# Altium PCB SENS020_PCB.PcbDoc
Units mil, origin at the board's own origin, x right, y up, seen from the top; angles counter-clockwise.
Board outline 1830 x 1450 mil, 2 copper layers (Top Layer, Bottom Layer), stack 62 mil thick; 50 components, 16 nets, 144 pads, 61 vias.
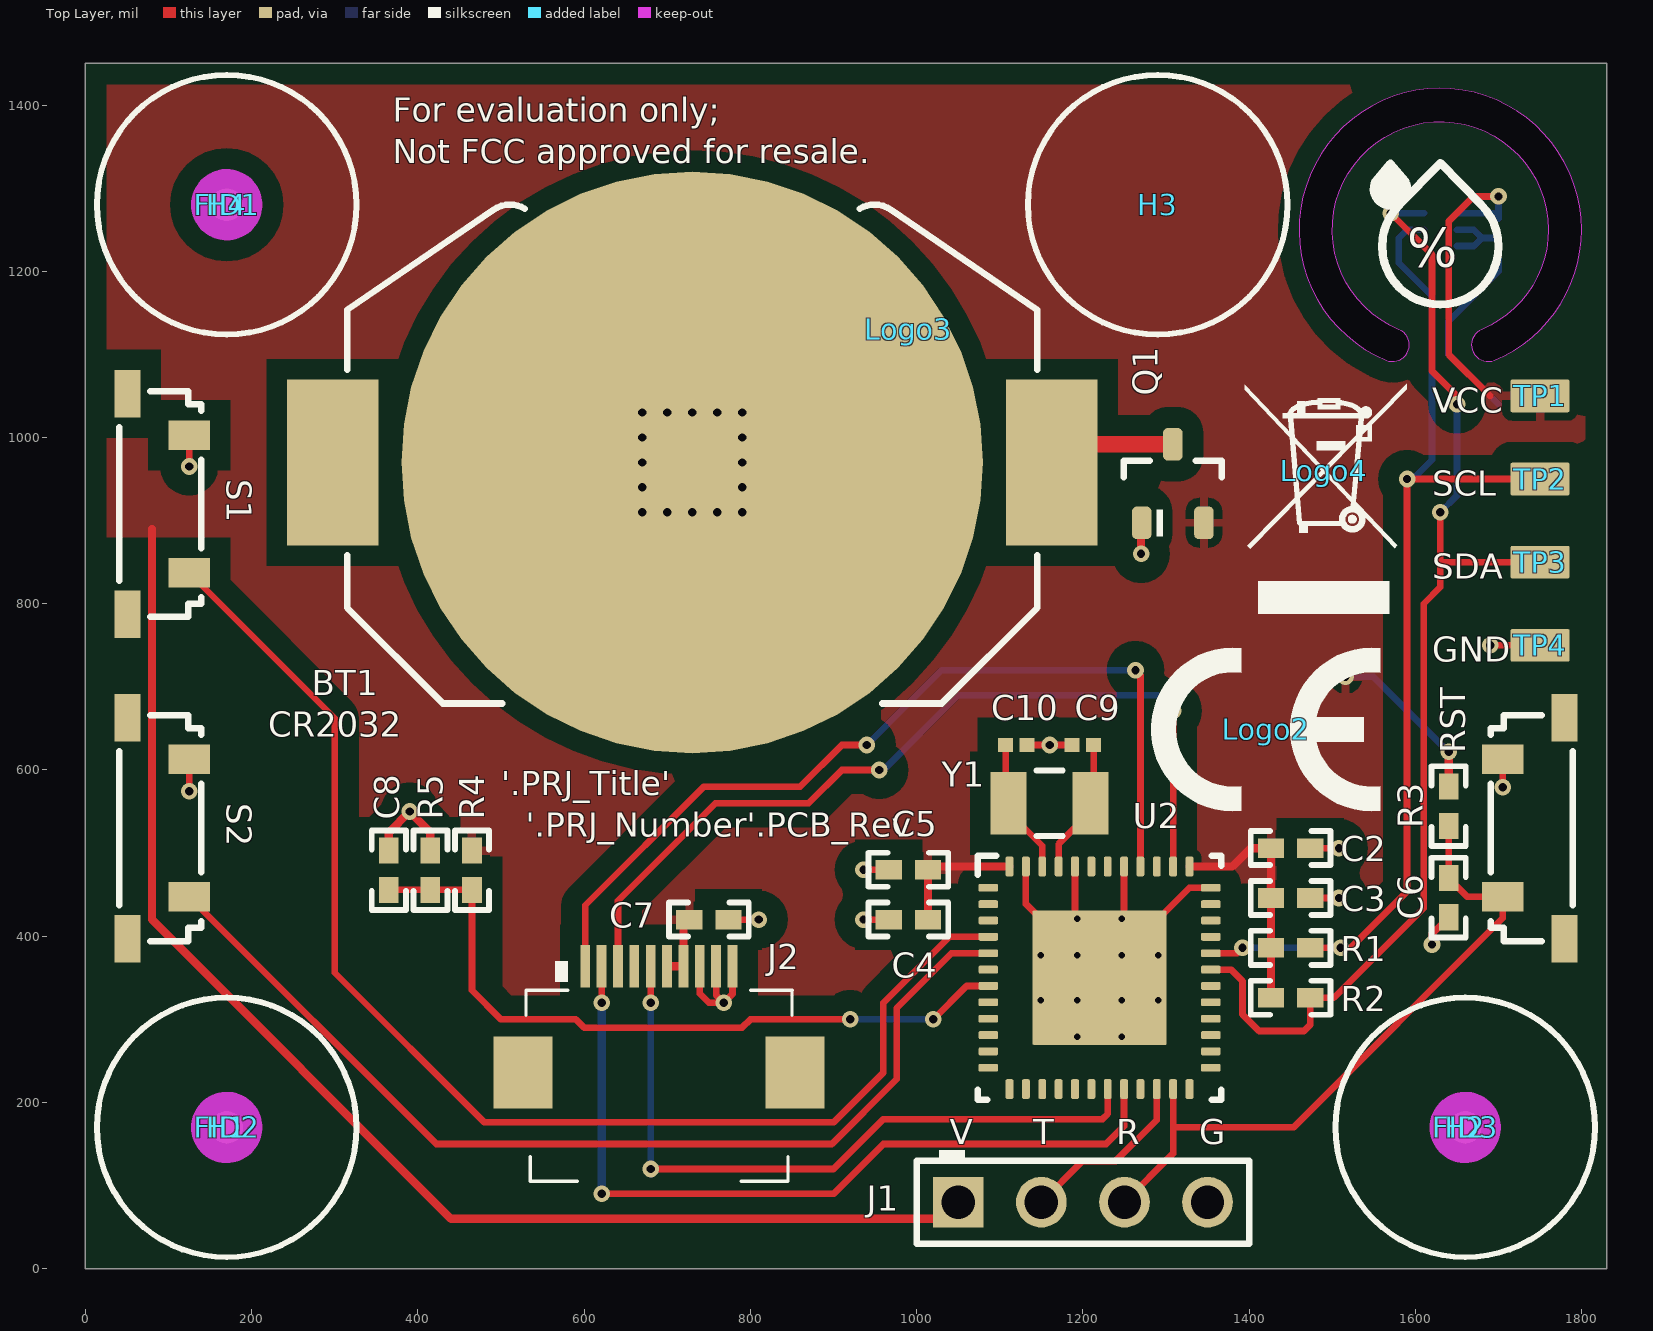
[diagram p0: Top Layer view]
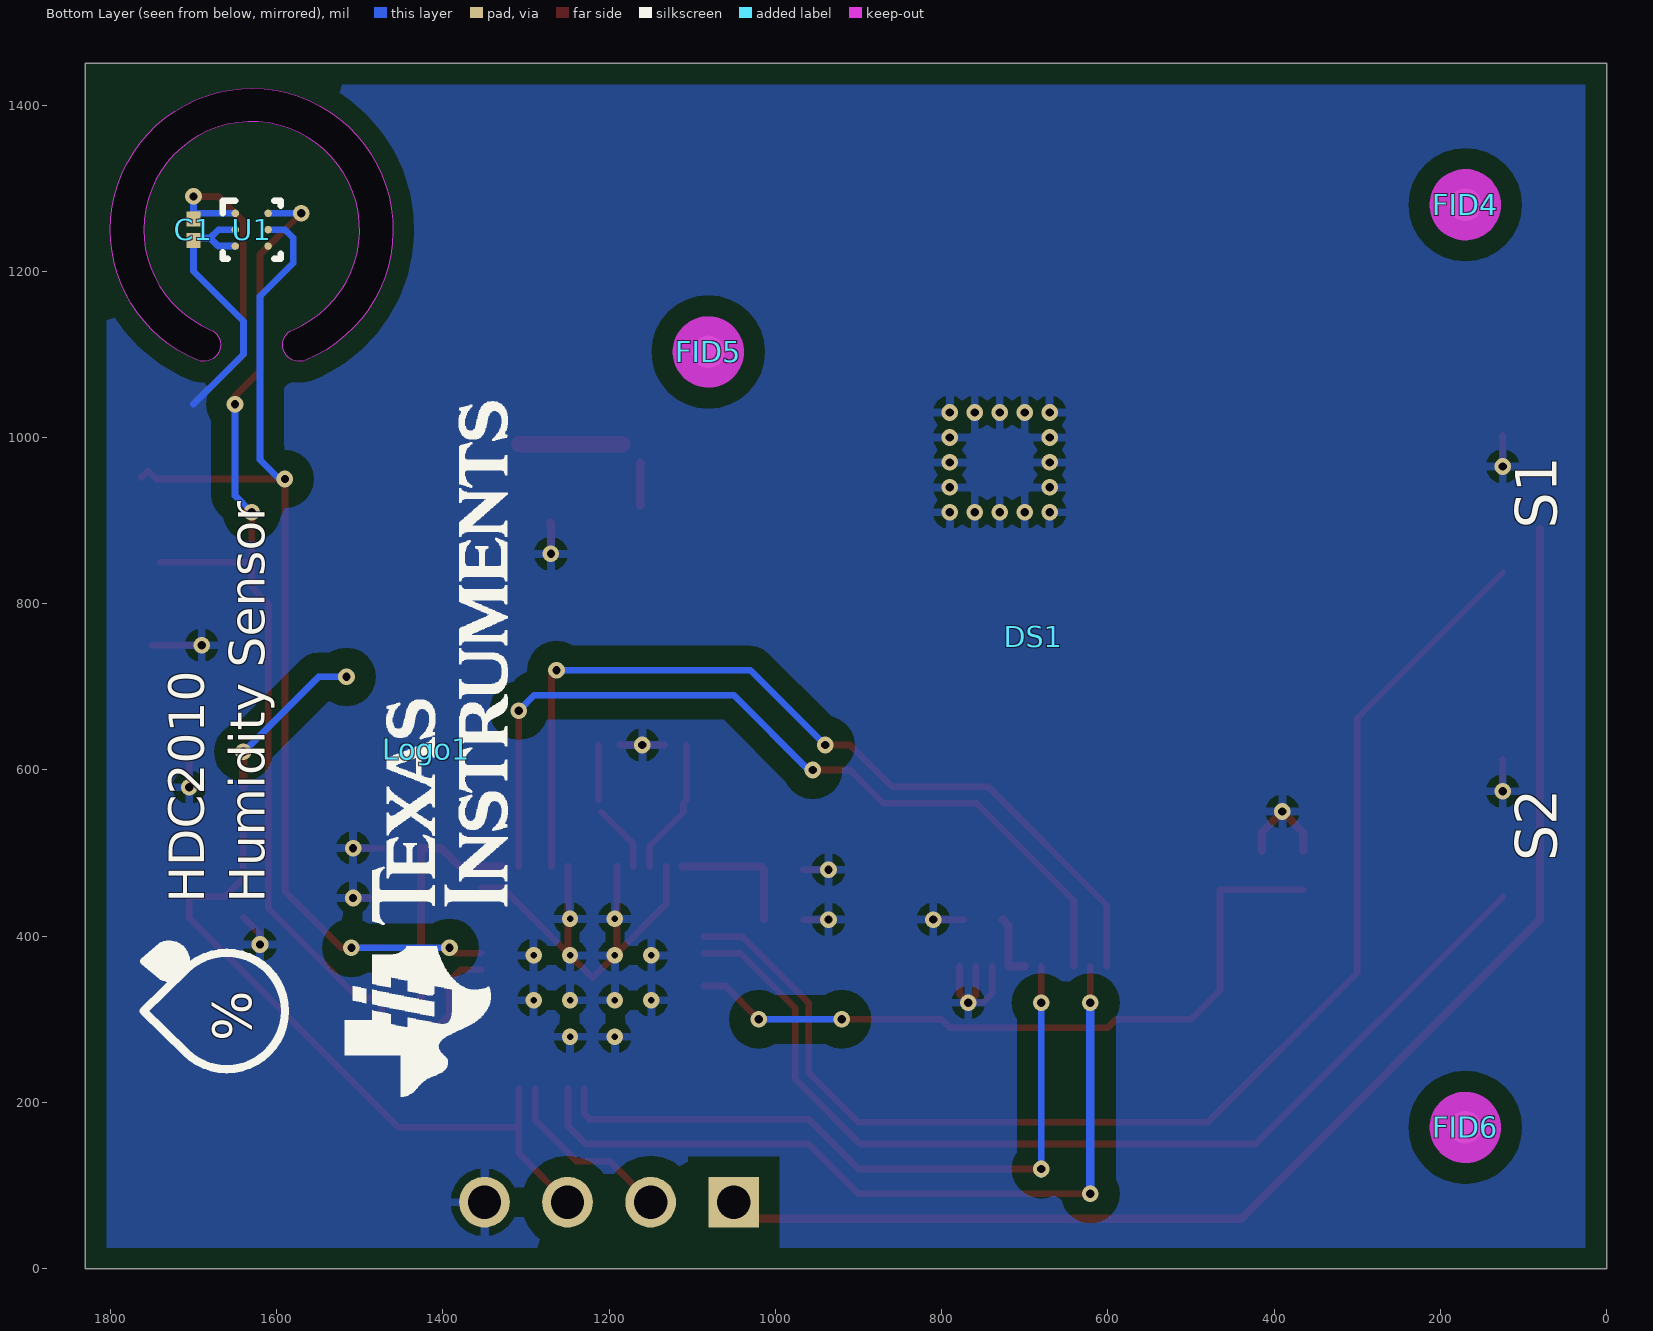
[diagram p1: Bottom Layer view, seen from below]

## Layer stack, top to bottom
Top Solder: solder mask 0.4, Solder Resist, Dk 3.5
Top Layer: signal copper 1.4
Dielectric1: core 59.2, FR-4, Dk 4.8
Bottom Layer: signal copper 1.4
Bottom Solder: solder mask 0.4, Solder Resist, Dk 3.5

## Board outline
0,0 0,1450 1830,1450 1830,0
cut-out: 1564.94,1092.93 ccw(c1572.6,1111.42) 1592.61,1111.42 ccw(c1572.6,1111.42) 1580.26,1129.91 cw(c1630,1250) 1759.99,1250 cw(c1630,1250) 1679.74,1129.91 ccw(c1687.4,1111.42) 1695.06,1092.93 ccw(c1630,1250) 1800.02,1250 ccw(c1630,1250)

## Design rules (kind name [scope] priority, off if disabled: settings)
AcuteAngle [All] p1: minimum=4.50000000000000E+0001 checktracksonly=FALSE
AssemblyTestPointUsage [All] p1: valid=2
BoardOutlineClearance BoardOutlineClearance_TO [OnLayer('Top Overlay') and not InRegion(1000,500,4000,800)] p1: gap=1 ignorepadtopadclearanceinfootprint=FALSE
BoardOutlineClearance BoardOutlineClearance_BO [OnLayer('Bottom Overlay') and not InRegion(1000,500,4000,800)] p2: gap=1 ignorepadtopadclearanceinfootprint=FALSE
BoardOutlineClearance BoardOutlineClearance_MountingHoles [OnCopper and InComponentClass('Mounting Holes')] p3: gap=40 ignorepadtopadclearanceinfootprint=FALSE
BoardOutlineClearance BoardOutlineClearance_Poly [OnCopper and IsPoly] p4: gap=25 ignorepadtopadclearanceinfootprint=FALSE
BoardOutlineClearance [OnCopper and Not InComponentClass('Logo') and not InComponentClass('FiducialMark') and not InPoly   and not InRegion(1000,500,4000,800)] p5: gap=10 ignorepadtopadclearanceinfootprint=FALSE
Clearance Clearance_Fiducial [IsKeepOut and InComponentClass('FiducialMark') vs IsPad and InComponentClass('FiducialMark')] p1: gap=0 ignorepadtopadclearanceinfootprint=FALSE
Clearance Clearance_Keepouts [((IsTrack Or IsArc) And Not InPoly) And IsFree and IsKeepOut vs ((IsTrack Or IsArc) And Not InPoly) And IsFree and IsKeepOut] p2: gap=0 ignorepadtopadclearanceinfootprint=FALSE
Clearance Clearance_Poly [InPolygon] p3: gap=25 ignorepadtopadclearanceinfootprint=FALSE except(0: Arc-Hole Track-Hole SMDPad-Hole THPad-Hole Via-Hole Fill-Hole Poly-Hole Region-Hole Text-Hole)
Clearance [All] p4: gap=7.87 ignorepadtopadclearanceinfootprint=FALSE except(0: Arc-Hole Track-Hole SMDPad-Hole THPad-Hole Via-Hole Fill-Hole Poly-Hole Region-Hole Text-Hole)
ComponentClearance ComponentClearance_FID [InComponentClass('FiducialMark') vs HasFootprint('Bumpon_SJ61A1')] p1: gap=0 collisioncheckmode=3 verticalgap=0 showdistances=FALSE
ComponentClearance ComponentClearance_LCD [HasFootprint('Sharp_LS013B7DH03')] p2: gap=0 collisioncheckmode=3 verticalgap=0 showdistances=FALSE
ComponentClearance ComponentClearance_MountingHoles_FiducialMarks [InComponentClass('Mounting Holes') vs InComponentClass('FiducialMark')] p3: gap=50 collisioncheckmode=3 verticalgap=10 showdistances=FALSE
ComponentClearance ComponentClearance_Shunt [InComponentClass('Header') vs InComponentClass('Shunt')] p4: gap=0 collisioncheckmode=3 verticalgap=0 showdistances=FALSE
ComponentClearance ComponentClearance_Logo [InComponentClass('Logo')] p5: gap=0 collisioncheckmode=3 verticalgap=0 showdistances=FALSE
ComponentClearance ComponentClearance_ScrewToNut [(HasFootprint('NY PMS 440 0025 PH')) vs (HasFootprint('Keystone_1902C'))] p6: gap=5 collisioncheckmode=3 verticalgap=10 showdistances=FALSE
ComponentClearance ComponentClearance_MountingHoles [InComponentClass('Mounting Holes')] p7: gap=250 collisioncheckmode=3 verticalgap=100000 showdistances=FALSE
ComponentClearance ComponentClearance_SmallPassives [HasFootprint('0201*') or HasFootprint('0402*') or HasFootprint('0508') or HasFootprint('0603*') or HasFootprint('0612') or HasFootprint('0805*') or HasFootprint('0815*') or HasFootprint('0830*') or HasFootprint('1206*') or HasFootprint('1210*') or HasFootprint('1808*') or HasFootprint('1812*') or HasFootprint('1825*') or HasFootprint('2010*') or HasFootprint('2220*') or HasFootprint('2225*') or HasFootprint('2512*') or HasFootprint('2728*') or HasFootprint('3518*') vs HasFootprint('0201*') or HasFootprint('0402*') or HasFootprint('0508') or HasFootprint('0603*') or HasFootprint('0612') or HasFootprint('0805*') or HasFootprint('0815*') or HasFootprint('0830*') or HasFootprint('1206*') or HasFootprint('1210*') or HasFootprint('1808*') or HasFootprint('1812*') or HasFootprint('1825*') or HasFootprint('2010*') or HasFootprint('2220*') or HasFootprint('2225*') or HasFootprint('2512*') or HasFootprint('2728*') or HasFootprint('3518*')] p8: gap=14.96 collisioncheckmode=3 verticalgap=10 showdistances=FALSE
ComponentClearance ComponentClearance_THtoSMT [IsThruComponent vs IsSMTComponent] p9: gap=40 collisioncheckmode=3 verticalgap=30 showdistances=FALSE
ComponentClearance ComponentClearance_THtoTH [IsThruComponent vs IsThruComponent] p10: gap=30 collisioncheckmode=3 verticalgap=30 showdistances=FALSE
ComponentClearance [All] p11: gap=30 collisioncheckmode=3 verticalgap=10 showdistances=FALSE
DiffPairsRouting [All] p1: maxlimit=100 minlimit=10 mostfreqgap=10 toplayer_minwidth=15 toplayer_maxwidth=15 toplayer_prefwidth=15 bottomlayer_minwidth=15 bottomlayer_maxwidth=15 bottomlayer_prefwidth=15 maxuncoupledlength=1000
FabricationTestPointUsage TestPointUsage [All] p1: valid=2 allowmultiple=FALSE
FabricationTestpoint Testpoint [All] p1: side=3 testpointundercomponent=TRUE minsize=40 maxsize=100 preferedsize=60 minholesize=0 maxholesize=40 preferedholesize=32 testpointgrid=1 allowsidetop=TRUE allowsidebottom=TRUE usegrid=TRUE gridtolerance=0.01
FanoutControl Fanout_LCC [IsLCC] p1: bgadir=Out bgaviamode=Centered fanoutstyle=Auto fanoutdirection=Alternating viagrid=1 // Fanout_LCC (Default Rule)
FanoutControl Fanout_BGA [IsBGA] p2: bgadir=Out bgaviamode=Centered fanoutstyle=Auto fanoutdirection=Alternating viagrid=1 // Fanout_BGA (Default Rule)
FanoutControl Fanout_Default [All] p4: bgadir=Out bgaviamode=Centered fanoutstyle=Auto fanoutdirection=Alternating viagrid=1 // Fanout_Default (Default Rule)
FanoutControl Fanout_Small [(CompPinCount < 5)] p5: bgadir=Out bgaviamode=Centered fanoutstyle=Auto fanoutdirection=OutThenIn viagrid=1 // Fanout_Small (Default Rule)
HoleSize [All] p1: absolutevalues=TRUE maxlimit=251 minlimit=7.87 maxpercent=80.000 minpercent=20.000
MinimumAnnularRing MinimumAnnularRing_ThermalPadVias [IsVia and InAnyComponent] p1: minimumring=5.91
MinimumAnnularRing [All] p2: minimumring=5
MinimumSolderMaskSliver MinimumSolderMaskSliver_Logo [InComponentClass('Logo') vs InComponentClass('Logo')] p1: minsoldermaskwidth=0.7
MinimumSolderMaskSliver [All] p2: minsoldermaskwidth=3.94
PlaneConnect [All] p1: planeconnectstyle=Relief reliefexpansion=10 reliefentries=4 reliefconductorwidth=10 reliefairgap=10
PolygonConnect [All] p1: connectstyle=Relief reliefconductorwidth=10 reliefentries=4 polygonreliefangle="90 Angle" airgapwidth=10
RoutingVias ThermalPadVias [IsVia and InAnyComponent] p1: holewidth=7.87 width=19.68 viastyle="Through Hole" minholewidth=7.87 minwidth=19.68 maxholewidth=12.99 maxwidth=23.62
RoutingVias [All] p2: holewidth=16 width=34 viastyle="Through Hole" minholewidth=7.87 minwidth=18 maxholewidth=40 maxwidth=65
SilkToBoardRegionClearance [Not ((IsComment or IsDesignator) And (Hide <> 'False')) and not InRegion(1000,500,4000,800)] p1:
SilkToSilkClearance SilkToSilkClearance_Pb-FreeLogo [(HasFootprint('Pb-Free_Overlay_Medium') OR HasFootprint('Pb-Free_Overlay_Small')) vs (HasFootprint('Pb-Free_Overlay_Medium') OR HasFootprint('Pb-Free_Overlay_Small'))] p1: silktosilkclearance=0
SilkToSilkClearance [All] p2: silktosilkclearance=4
SilkToSolderMaskClearance SilkToComponentPadClearance [(IsPad or IsFill or IsRegion) and InAnycomponent] p1: minsilkscreentomaskgap=5 clearancetoexposedcopper=TRUE
SilkToSolderMaskClearance "Silk to Solder Mask Opening" [All] p2: minsilkscreentomaskgap=4 clearancetoexposedcopper=FALSE
SolderMaskExpansion [All] p1: expansion=1.97
Width [All] p1: maxlimit=100 minlimit=6 preferedwidth=10 checkconnectedcopper=TRUE
15 further rules are at their usual default settings.

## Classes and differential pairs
component class Header: J1
component class AssemblyNote: ZZ1 ZZ2 ZZ3 ZZ4 ZZ5 ZZ6
component class FiducialMark: FID1 FID2 FID3 FID4 FID5 FID6
component class SENS020_Hardware: FID1 FID2 FID3 FID4 FID5 FID6 H1 H2 H3 H4 Logo1 Logo2 Logo3 Logo4 ZZ1 ZZ2 ZZ3 ZZ4 ZZ5 ZZ6
component class Logo: Logo1
component class SENS020_SCH: BT1 C1 C2 C3 C4 C5 C6 C7 C8 C9 C10 DS1 J1 J2 Q1 R1 R2 R3 R4 R5 RST S1 S2 TP1 TP2 TP3 TP4 U1 U2 Y1

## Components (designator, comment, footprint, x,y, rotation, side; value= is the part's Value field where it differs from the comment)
BT1 "BK-912" MPD_BK-912 730,970 r180 top locked
C1 "GRM033R61C104KE84D" 0201_033 1700,1250 r270 bottom value=0.1uF
C2 "GRM155R61A104KA01D" 0402 1450,506 r0 top value=0.1uF
C3 "GRM155R60J105KE19D" 0402 1450,446 r0 top value=1uF
C4 "GRM155R61A104KA01D" 0402 990,420 r180 top value=0.1uF
C5 "GRM155R60J105KE19D" 0402 990,480 r180 top value=1uF
C6 "GRM155R60J222KA01D" 0402 1640,446.38 r270 top value=2200pF
C7 "GRM155R61A104KA01D" 0402 750,420 r0 top value=0.1uF
C8 "GRM155R61A104KA01D" 0402 365,479.37 r90 top value=0.1uF
C9 "GRM0335C1H120JA01D" 0201 1200,630 r180 top value=12pF
C10 "GRM0335C1H120JA01D" 0201 1120,630 r0 top value=12pF
DS1 "LS013B7DH03" Sharp_LS013B7DH03 690,760 r180 bottom locked
FID1 "Fiducial" Fiducial10-20 170,1280 r0 top
FID2 "Fiducial" Fiducial10-20 170,170 r0 top
FID3 "Fiducial" Fiducial10-20 1660,170 r0 top
FID4 "Fiducial" Fiducial10-20 170,1280 r180 bottom
FID5 "Fiducial" Fiducial10-20 1080.71,1102.95 r180 bottom
FID6 "Fiducial" Fiducial10-20 170,170 r180 bottom
H1 "SJ61A1" Bumpon_SJ61A1 170,170 r0 top
H2 "SJ61A1" Bumpon_SJ61A1 1660,170 r0 top
H3 "SJ61A1" Bumpon_SJ61A1 1290,1280 r0 top
H4 "SJ61A1" Bumpon_SJ61A1 170,1280 r0 top
J1 "PBC04SAAN" Sullins_xxC04SAAN 1200,80 r0 top
J2 "FH12-10S-0.5SH[55]" Hirose_FH12-10S-0_5SH[55] 690,300 r0 top
Logo1 "Texas Instruments" TI_Stacked_Overlay_Small 1420,625.13 r90 bottom
Logo2 "CE Mark" CE_Mark_5mm 1420,648.76 r0 top (schematic designator LOGO2)
Logo3 "FCC disclaimer" FCC_disclaimer 990,1130 r0 top
Logo4 "WEEE logo" WEEE_Minimum 1490,960 r0 top
Q1 "SI2323DS" SOT-23 1308.19,944.58 r90 top value=-20V
R1 "CRCW040210K0JNED" 0402 1450,386 r180 top value=10k
R2 "CRCW040210K0JNED" 0402 1450,326 r180 top value=10k
R3 "CRCW040233K0JNED" 0402 1640,556.38 r90 top value=33k
R4 "CRCW04022M00FKED" 0402 465,479.37 r90 top value=2.00Meg
R5 "CRCW04022M00FKED" 0402 415,479.37 r270 top value=2.00Meg
RST "TL3330AF260QG" SW_TL3330 1740,530 r90 top
S1 "TL3330AF260QG" SW_TL3330 90,920 r270 top
S2 "TL3330AF260QG" SW_TL3330 90,530 r270 top
TP1 "S2761-46R" Harwin_S2761-46R 1750,1050 r0 top
TP2 "S2761-46R" Harwin_S2761-46R 1750,950 r0 top
TP3 "S2761-46R" Harwin_S2761-46R 1750,850 r0 top
TP4 "S2761-46R" Harwin_S2761-46R 1750,750 r0 top
U1 "HDC2010YPAR" YPA0006ABAB 1630,1250 r180 bottom
U2 "MSP430FR5969IRGZR" RGZ0048B 1220,350 r0 top
Y1 "ABS07-32.768KHZ-T" XTAL_ABS07 1160,560 r0 top
ZZ1 "These assemblies are ESD sensitive, ESD precautions shall be observed." AssemblyNote 180,3050 r0 top
ZZ2 "These assemblies must be clean and free from flux and all contaminants. Use of no clean flux is not acceptable." AssemblyNote 180,2970 r0 top
ZZ3 "These assemblies must comply with workmanship standards IPC-A-610 Class 2, unless otherwise specified." AssemblyNote 180,2880 r0 top
ZZ4 "These assemblies must not be washed after the HDC device is mounted." AssemblyNoteLabel 180,2710 r0 top
ZZ5 "These assemblies must not have flux contamination between the HDC device and the PCB." AssemblyNoteLabel 180,2630 r0 top
ZZ6 "Recommended to assemble and wash top side components before assembling HDC on bottom side." AssemblyNoteLabel 180,2550 r0 top

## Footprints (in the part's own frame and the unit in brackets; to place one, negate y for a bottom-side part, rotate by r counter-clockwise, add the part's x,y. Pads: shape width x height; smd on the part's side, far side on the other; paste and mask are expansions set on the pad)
0201 [mm] "Data from Kemet datasheet CC101_COM dated 7/28/11"
  rect 0.46x0.42 smd mask+0.048: 1(-0.33,0) 2(0.33,0)
  body extent -0.31,-0.16 0.31,0.16, height 0.26
0201_033 [mm] "SMD, 2-Leads, Height 0.33mm"
  rect 0.46x0.42 smd mask+0.048: 1(-0.33,0) 2(0.33,0)
  body extent -0.31,-0.16 0.31,0.16, height 0.33
0402 [mm] "0402 from SM-752 data"
  rect 0.8x0.6 smd: 1(-0.6,0) 2(0.6,0)
  silkscreen extent -1.22,-0.52 1.22,0.52, body extent -0.55,-0.3 0.55,0.3, height 0.6
AssemblyNote [mil] "Assembly Note"
AssemblyNoteLabel [mil] "Assembly Note for PCB Labels"
Bumpon_SJ61A1 [mil] "3M Cylindrical Bumpon black"
  round 1 on Mech3: 0(0,0)
  silkscreen extent -156,-156 156,156, body extent -156,-155 156,156, height 201
CE_Mark_5mm [mil] "Minimum text height for CE Mark"
  silkscreen extent -138,-98 138,98
FCC_disclaimer [mil]
Fiducial10-20 [mm]
  round 1 smd mask+0.5: 1(0,0)
  Top Layer keep-out circle w1.178: c0,0 r0.5
Harwin_S2761-46R [mm] "Natural PC Test Point Brass, SMT"
  rrect10% 1.8x1 smd: 1(0,0)
  body extent -0.8,-0.4 0.8,0.4, height 1.15
Hirose_FH12-10S-0_5SH[55] [mm] "Hirose, footprint recommended"
  rect 0.3x1.3 smd: 1(-2.254,1.626) 2(-1.754,1.626) 3(-1.254,1.626) 4(-0.754,1.626) 5(-0.253,1.626) 6(0.246,1.626) 7(0.746,1.626) 8(1.246,1.626) 9(1.746,1.626) 10(2.247,1.626)
  rect 1.8x2.2 smd: M1(-4.153,-1.622) M2(4.153,-1.626)
  silkscreen extent -4.06,-4.95 4.07,1.78, body extent -4.55,-4.88 4.56,0.84, height 2
MPD_BK-912 [mm] "Battery Holder for CR2032, SMT"
  rect 2.79x5.08 smd: 1(-10.985,0) 2(10.985,0)
  round 17.78 smd paste-9: 3(0,0)
  silkscreen extent -10.54,-7.88 10.54,7.37, body extent -11.43,-7.88 11.43,7.37, height 4.33
RGZ0048B [mm] "QFN, 48-Leads, Body 7x7mm, Pitch 0.5mm, Thermal Pad 5.15x5.15mm, TI Recommended"
  rrect42% 0.6x0.24 smd: 1(-3.4,2.75) 2(-3.4,2.25) 3(-3.4,1.75) 4(-3.4,1.25) 5(-3.4,0.75) 6(-3.4,0.25) 7(-3.4,-0.25) 8(-3.4,-0.75) 9(-3.4,-1.25) 10(-3.4,-1.75) 11(-3.4,-2.25) 12(-3.4,-2.75) 25(3.4,-2.75) 26(3.4,-2.25) 27(3.4,-1.75) 28(3.4,-1.25) 29(3.4,-0.75) 30(3.4,-0.25) 31(3.4,0.25) 32(3.4,0.75) 33(3.4,1.25) 34(3.4,1.75) 35(3.4,2.25) 36(3.4,2.75)
  rrect42% 0.24x0.6 smd: 13(-2.75,-3.4) 14(-2.25,-3.4) 15(-1.75,-3.4) 16(-1.25,-3.4) 17(-0.75,-3.4) 18(-0.25,-3.4) 19(0.25,-3.4) 20(0.75,-3.4) 21(1.25,-3.4) 22(1.75,-3.4) 23(2.25,-3.4) 24(2.75,-3.4) 37(2.75,3.4) 38(2.25,3.4) 39(1.75,3.4) 40(1.25,3.4) 41(0.75,3.4) 42(0.25,3.4) 43(-0.25,3.4) 44(-0.75,3.4) 45(-1.25,3.4) 46(-1.75,3.4) 47(-2.25,3.4) 48(-2.75,3.4)
  rrect9% 1.17x1.17 on Top Paste: 49(-1.37,-1.37) 49(-1.37,0) 49(-1.37,1.37) 49(0,-1.37) 49(0,0) 49(0,1.37) 49(1.37,-1.37) 49(1.37,0) 49(1.37,1.37)
  rrect2% 4.1x4.1 smd paste-2.575: 49(0,0)
  silkscreen extent -3.72,-3.72 3.72,3.72, body extent -3.5,-3.5 3.5,3.5, height 1.01
Sharp_LS013B7DH03 [mil] "LCD Display Dot Pixels 128x128"
  body extent -524,-1167 524,563, height 29
SOT-23 [mm] "SOT23, 3-Leads, Body 2.9x1.3mm, Pitch 0.95mm, Lead Span 2.5mm, IPC Medium Density"
  rrect50% 1x0.6 smd: 1(-1.2,0.95) 2(-1.2,-0.95) 3(1.2,0)
  silkscreen extent -1.62,-1.5 0.7,1.5, body extent -1.16,-1.45 1.21,1.45, height 1
Sullins_xxC04SAAN [mm] "Header, 2.54 mm, 4x1, TH"
  rect 1.55x1.55 hole 1.016: 1(-3.81,0)
  round 1.55 hole 1.016: 2(-1.27,0) 3(1.27,0) 4(3.81,0)
  silkscreen extent -5.08,-1.27 5.08,1.6, body extent -5.08,-1.27 5.08,1.27, height 8.38
SW_TL3330 [mm] "SMD, 4-Leads, Body 7.8x3.5mm"
  rect 0.9x1.27 smd: 1(-2.1,0.885) 2(2.1,0.885)
  rect 1.45x0.8 smd: 3(-3.375,-1) 4(3.375,-1)
  silkscreen extent -3.45,-1.25 3.45,1.25, body extent -3.9,-2.25 3.9,1.35, height 3.5
TI_Stacked_Overlay_Small [mil]
  silkscreen extent -418,-98 418,98
WEEE_Minimum [mil] "WEEElie bin"
  silkscreen extent -95,-172 99,104
XTAL_ABS07 [mm] "ABRACON"
  rect 1.1x1.9 smd: 1(-1.25,0) 2(1.25,0)
  silkscreen extent -0.4,-1 0.4,1, body extent -1.65,-0.8 1.65,0.8, height 0.9
YPA0006ABAB [mm] "BGA, 6-Leads, Body1.505x1.505mm, Pitch 0.5mm"
  round 0.23 smd paste-0.13 mask+0.038: A1(-0.5,0.5) A2(0.5,0.5) B1(-0.5,0) B2(0.5,0) C1(-0.5,-0.5) C2(0.5,-0.5)
  silkscreen extent -0.89,-0.89 0.89,0.89, body extent -0.75,-0.75 0.75,0.75, height 0.68

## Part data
BT1: library part CMP-0003749-2, "Battery Holder for CR2032, SMT", Manufacturer="Memory Protection Devices", Supplier Part Number 1=BK-912-ND
C1: library part CMP-0009717-2, "CAP, CERM, 0.1 uF, 16 V, +/- 10%, X5R, 0201", Cap_Case=0201, Manufacturer=MuRata, Supplier Part Number 1=490-9985-1-ND, TempCo=X5R, Tolerance_%=10%, Value1=Unknown, Value2=16V, ValueDisplayed=0.1uF
C2 C4 C7 C8: library part CMP-0006562-2, "CAP, CERM, 0.1 uF, 10 V, +/- 10%, X5R, 0402", Cap_Case=0402, Manufacturer=MuRata, Supplier Part Number 1=490-1318-1-ND, TempCo=X5R, Tolerance_%=10%, Value1=Unknown, Value2=10V, ValueDisplayed=0.1uF
C3 C5: library part CMP-0006532-2, "CAP, CERM, 1 uF, 6.3 V, +/- 10%, X5R, 0402", Cap_Case=0402, Manufacturer=MuRata, Supplier Part Number 1=490-1320-1-ND, TempCo=X5R, Tolerance_%=10%, Value1=Unknown, Value2=6.3V, ValueDisplayed=1uF
C6: library part CMP-0006540-2, "CAP, CERM, 2200 pF, 6.3 V, +/- 10%, X5R, 0402", Cap_Case=0402, Manufacturer=MuRata, Supplier Part Number 1=GRM155R60J222KA01D-ND, TempCo=X5R, Tolerance_%=10%, Value1=Unknown, Value2=6.3V, ValueDisplayed=2200pF
C9 C10: library part CMP-0009664-3, "CAP, CERM, 12 pF, 50 V, +/- 5%, C0G/NP0, 0201", Cap_Case=0201, Manufacturer=MuRata, Supplier Part Number 1=490-6114-1-ND, TempCo=C0G/NP0, Tolerance_%=5%, Value1=Unknown, Value2=50V, ValueDisplayed=12pF
DS1: library part CMP-0067626-1, "LCD Display Dot Pixels 128x128", Manufacturer="Sharp Microelectronics", Supplier Part Number 1=425-2903-ND
FID1 FID2 FID3 FID4 FID5 FID6: library part CMP-0077181-1, "Fiducial mark.  There is nothing to buy or mount.", Manufacturer=N/A
H1 H2 H3 H4: library part CMP-0003621-1, "Bumpon, Cylindrical, 0.312 X 0.200, Black", Manufacturer=3M, Supplier Part Number 1=SJ5746-0-ND
J1: library part CMP-0054583-1, "Header, 2.54 mm, 4x1, Gold, TH", Color=Black, Current_A=3A, Manufacturer="Sullins Connector Solutions", Supplier Part Number 1=S1011E-04-ND, Voltage_V=1.8kV
J2: library part CMP-0075009-2, "Connector, FPC 10 Pos. 9.1x2.0x5.6 mm", Manufacturer="Hirose Electric Co. Ltd.", PartNumber=FH12-10S-0.5SH(55), Supplier Part Number 1=HFJ110CT-ND
Logo1: library part CMP-0074838-1, "Texas Instrument Corporate Signature"
Logo2: library part CMP-0074844-1
Logo3: library part CMP-0074847-1, "FCC_disclaimer"
Logo4: library part CMP-0074769-1
Q1: library part CMP-0000092-2, "MOSFET, P-CH, -20 V, -3.7 A, SOT-23", Alternate Manufacturer=None, Manufacturer=Vishay-Siliconix, Value1=0.03, Value2="12.5 nC"
R1 R2: library part CMP-0026825-4, "RES, 10 k, 5%, 0.063 W, 0402", Manufacturer=Vishay-Dale, Power_W=63mW, Supplier Part Number 1=541-10KJCT-ND, TempCo="200 ppm/C", Tolerance_%=5%, Value2=0.063W, Value_Code=10k0, ValueDisplayed=10k
R3: library part CMP-0026907-2, "RES, 33 k, 5%, 0.063 W, 0402", Manufacturer=Vishay-Dale, Power_W=63mW, Supplier Part Number 1=541-33KJCT-ND, TempCo="200 ppm/C", Tolerance_%=5%, Value2=0.063W, Value_Code=33k0, ValueDisplayed=33k
R4 R5: library part CMP-0026245-1, "RES, 2.00 M, 1%, 0.063 W, 0402", Manufacturer=Vishay-Dale, Power_W=63mW, Supplier Part Number 1=541-2.00MLCT-ND, TempCo="100 ppm/C", Tolerance_%=1%, Value2=0.063W, Value_Code=2M00, ValueDisplayed=2.00M
RST S1 S2: library part CMP-0002231-1, "Switch, SPST-NO,  1 Pos, 0.05A, 12VDC, SMD", CurrentRating_mA=50A, Manufacturer=E-Switch, Supplier Part Number 1=EG4389CT-ND
TP1 TP2 TP3 TP4: library part CMP-0067619-1, "Natural PC Test Point Brass, SMT", Manufacturer=Harwin, Supplier Part Number 1=952-2665-1-ND
U1: library part CMP-0014223-2, "HDC2010 Low Power Humidity and Temperature Digital Sensor, YPA0006ABAB (DSBGA-6)", Alternate Manufacturer="Texas Instruments", Alternate PartNumber=HDC2010YPAT
U2: library part CMP-0066503-2, "MSP430FR5969 16 MHz Ultra-Low-Power Microcontroller featuring 64 KB FRAM, 2 KB SRAM, 40 IO, RGZ0048B (VQFN-48)", Alternate Manufacturer="Texas Instruments", Alternate PartNumber=MSP430FR5969IRGZT
Y1: library part CMP-0004628-3, "CRYSTAL, 32.768KHz, 12.5PF, SMD", Frequency_Fixed=32.768kHz, Frequency Stability=+/-20ppm, Manufacturer="Abracon Corporation", Supplier Part Number 1=535-9542-1-ND
ZZ1: library part CMP-0077236-1
ZZ2: library part CMP-0077237-1
ZZ3: library part CMP-0077238-1
ZZ4 ZZ5 ZZ6: library part CMP-0003616-3, "This Assembly Note is for PCB labels only"

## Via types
v1: diameter 20, hole 10, Top Layer to Bottom Layer, tented both sides, 47 vias
v2: diameter 19.68, hole 7.87, Top Layer to Bottom Layer, 12 vias
v3: diameter 20, hole 10, Top Layer to Bottom Layer, 2 vias

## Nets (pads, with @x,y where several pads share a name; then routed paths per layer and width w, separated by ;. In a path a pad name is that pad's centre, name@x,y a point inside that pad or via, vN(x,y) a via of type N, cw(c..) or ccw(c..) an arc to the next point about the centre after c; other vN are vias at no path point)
DISP: J2.5 U2.19 | length 857.8
  Top Layer w8: v1(680,120) 900,120 960,180 1223.62,180 1229.84,186.22 U2.19 ; v1(680.02,320) J2.5
  Bottom Layer w8: v1@680.02,113.37 v1(680.02,320)
GND: BT1.3 C1.2 C2.2 C3.2 C4.2 C5.2 C6.2 C7.2 C8.2 C9.2 C10.2 J1.4 J2.8 J2.9 J2.10 Q1.1 R5.1 RST.2 S1.1 S2.1 TP4.1 U1.B1 U1.C1 U2.36 U2.41 U2.44 U2.47 U2.49@1220,350 | length 1635.9
  Top Layer w8: v1(124.84,574.37) S2.1 ; v1(124.84,965.16) S1.1 ; J2.8 739.07,330.93 750,320 v1(768,320) ; J2.9 758.76,329.24 v1(768,320) ; C7.2 v1(810,420) ; J2.10 778.44,330.44 v1(768,320) ; v1(936,420) C4.2 ; v1(936,480) C5.2 ; U2.47 1131.42,438.58 U2.49@1190.47,379.53 ; C10.2 v3(1160,630) C9.2 ; U2.44 U2.49@1190.47,379.53 ; U2.41 U2.49@1249.53,379.53 ; U2.36 1328.27,458.27 U2.49@1249.53,379.53 ; C3.2 v1(1508,446) ; C2.2 v1(1508,506) ; v1(1620,390) 1620,402.76 C6.2 ; v1(1690,750) TP4.1 ; v1(1705.16,579.25) RST.2 ; U2.49@1190.47,379.53 v2(1193.03,376.97) 1220,350 v2(1246.97,376.97) U2.49@1249.53,379.53
  Top Layer w10: C8.2 365,525 v1(390,550) 415,525 R5.1 ; v1(1270,860) 1270,896.55 Q1.1
  Bottom Layer w8: U1.C1 1670.32,1230.32 1680,1240 ; U1.B1 1670,1250 1680,1240 ; C1.2@1697.01,1240 1680,1240 ; 1700,1040 1639.83,1100.17 1639.83,1139.83 1700,1200 C1.2
  other v1: 670,910 700,910 730,910 760,910 790,910 670,940 790,940 670,970 790,970 670,1000 790,1000 670,1030 700,1030 730,1030 760,1030 790,1030
  other v2: 1193.03,279.13 1246.97,279.13 1149.13,323.03 1193.03,323.03 1246.97,323.03 1290.87,323.03 1149.13,376.97 1290.87,376.97 1193.03,420.87 1246.97,420.87
NetBT1_1: BT1.1 Q1.3 | length 176.4
  Top Layer w10: BT1.1@1162.48,917.52 BT1.1
  Top Layer w20: BT1.1@1184.31,991.83 Q1.3
NetC9_1: C9.1 U2.45 Y1.2 | length 147.5
  Top Layer w8: U2.45 1170.79,510.79 Y1.2@1209.21,549.21 ; Y1.2@1212.99,563.78 C9.1
NetC10_1: C10.1 U2.46 Y1.1 | length 159.1
  Top Layer w8: Y1.1@1107.01,563.78 C10.1 ; Y1.1 1110.79,549.21 1151.1,508.9 U2.46
NetS1_2: S1.2 U2.4 | length 1556.2
  Top Layer w8: S1.2 300,662.17 300,356 480,176 900,176 960,236 960,320 1039.21,399.21 U2.4
NetS2_2: S2.2 U2.5 | length 1229.6
  Top Layer w8: S2.2 422.17,150 898,150 975.87,227.87 975.87,313.42 1041.98,379.53 U2.5
RST: C6.1 J1.3 R3.1 RST.1 U2.23 | length 844.1
  Top Layer w8: J1.3@1270,80 J1.3 1308.58,138.58 1308.58,170 ; U2.23 1308.58,170 ; R3.1 C6.1 1662.68,447.32 RST.1 1705.16,421.75 1453.41,170 1308.58,170
SCL: R1.1 TP2.1 U1.B2 U2.32 | length 1330.5
  Top Layer w8: U2.32 1385.53,379.53 v1(1392,386) ; R1.1 v1(1510,386) 1522,386 1590,454 v1(1590,950) 1744.78,950 1754.78,960 TP2.1@1762.97,951.81
  Bottom Layer w8: v1(1392,386) v1(1510,386) ; v1@1596.76,950 1620,973.24 1620,1170 1580,1210 1580,1240 1590,1250 U1.B2
SDA: R2.1 TP3.1 U1.A2 U2.31 | length 1425.7
  Top Layer w8: U2.31 1378.16,359.84 1392,346 1392,306 1412,286 1466,286 1473.62,293.62 R2.1 1502,326 1610,434 1610,800 1630,820 1630,850 ; v1(1570.32,1269.68) 1620,1220 1620,1080 1650,1050 v1(1650,1040) ; v1(1630,910) 1630,850 ; TP3.1@1740,850 1630,850
  Bottom Layer w8: v1(1570.32,1269.68) U1.A2 ; v1(1630,910) 1650,930 v1(1650,1040)
SPI_CLK: J2.1 U2.40 | length 1089
  Top Layer w8: J2.1 601.28,437.28 744,580 860,580 910,630 v1(940,630) ; v1@1264.63,718.61 1269.21,714.02 U2.40
  Bottom Layer w8: v1(940,630) 1030,720 v1(1263.24,720)
SPI_CS: J2.3 U2.38 | length 1044.3
  Top Layer w8: J2.3 640.65,442.65 758,560 870,560 910,600 v1(955,600) ; U2.38 v1(1308.58,671.42)
  Bottom Layer w8: v1(955,600) 960,600 1050,690 1290,690 v1(1308.58,671.42)
SPI_SI: J2.2 U2.20 | length 981
  Top Layer w8: v1(620.96,90) 900,90 960,150 1228,150 1249.53,171.53 U2.20 ; v1(620.96,320) J2.2
  Bottom Layer w10: v1(620.96,90) v1(620.96,320)
TEST: J1.2 U2.22 | length 217.1
  Top Layer w8: J1.2 1199.37,129.37 1239.37,129.37 1288.9,178.9 U2.22
VCC: C1.1 C2.1 C3.1 C4.1 C5.1 C7.1 J1.1 J2.6 J2.7 Q1.2 R1.2 R2.2 R3.2 R4.2 TP1.1 U1.A1 U2.37 U2.48 | length 2709.4
  Top Layer w8: J1.1@1030,60 J1.1 ; 1690,1050 1640,1100 1640,1260 1670,1290 v1(1700,1290)
  Top Layer w10: 80,890 80,420 440,60 J1.1@1030,60 ; J2.6 J2.7 719.39,413.01 C7.1 ; C4.1 C5.1 1017.48,483.86 U2.48 ; U2.37 1379.86,483.86 1402,506 C2.1 C3.1 R2.2 ; R3.2 v1(1640,621.81)
  Bottom Layer w8: v1(1516,712) 1549.81,712 v1(1640,621.81) ; U1.A1 1693.31,1269.68 C1.1 v1(1700,1290)
VCC-MONITOR: C8.1 R4.1 R5.2 U2.7 | length 881.3
  Top Layer w8: C8.1 R4.1 465,335 500,300 590,300 600,290 790,290 800,300 v1(920,300) ; v3(1020,300) 1060.16,340.16 U2.7
  Bottom Layer w8: v1(920,300) v3(1020,300)
pads on no net: BT1.2 FID1.1 FID2.1 FID3.1 FID4.1 FID5.1 FID6.1 H1.0 H2.0 H3.0 H4.0 J2.4 J2.M1 J2.M2 RST.3 RST.4 S1.3 S1.4 S2.3 S2.4 U1.C2 U2.1 U2.2 U2.3 U2.6 U2.8 U2.9 U2.10 U2.11 U2.12 U2.13 U2.14 U2.15 U2.16 U2.17 U2.18 U2.21 U2.24 U2.25 U2.26 U2.27 U2.28 U2.29 U2.30 U2.33 U2.34 U2.35 U2.39 U2.42 U2.43 U2.49@1166.06,296.06 U2.49@1166.06,350 U2.49@1166.06,403.94 U2.49@1220,296.06 U2.49@1220,350 U2.49@1220,403.94 U2.49@1273.94,296.06 U2.49@1273.94,350 U2.49@1273.94,403.94

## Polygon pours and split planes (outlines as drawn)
GND on Bottom Layer "BOTTOM_LAYER_GND_P006" (solid, remove dead copper, pour order 6): 0,0 1830,0 1830,1450 0,1450 0,0
VCC on Top Layer "TOP_LAYER_VCC_P008" (solid, remove dead copper, pour order 8): 0,0 0,1450 1830,1450 1830,0 0,0
no net on Top Overlay "NONET_L-01_P-001" (none, remove dead copper): 1580.5,1279.5 ccw(c1630,1230) 1679.5,1279.5 1630,1330
no net on Top Overlay "NONET_L-01_P-001" (none, remove dead copper): 1580.5,1279.5 ccw(c1630,1230) 1679.5,1279.5 1630,1330
no net on Bottom Overlay "NONET_L-01_P-001" (none, remove dead copper): 1709.5,359.5 ccw(c1660,310) 1709.5,260.5 1760,310
no net on Bottom Overlay "NONET_L-01_P-001" (none, remove dead copper): 1709.5,359.5 ccw(c1660,310) 1709.5,260.5 1760,310

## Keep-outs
Keep-Out Layer:
  text ".Layer_Name" at 577,-1628.49 h60

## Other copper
Top Layer:
  pour cut-out: 20,880 150,880 150,420 501.81,420 501.81,170 1010,170 1010,20 20,20
  pour cut-out: 1630,1100 cw(c1630,1250) 1480,1250 cw(c1630,1250) 1630,1400 cw(c1630,1250) 1780,1250 cw(c1630,1250)
  text ".Layer_Name" at 577,-1628.49 h60
Bottom Layer:
  pour cut-out: 1630,1100 cw(c1630,1250) 1480,1250 cw(c1630,1250) 1630,1400 cw(c1630,1250) 1780,1250 cw(c1630,1250)
  text ".Layer_Name" at 577,-1628.49 h60

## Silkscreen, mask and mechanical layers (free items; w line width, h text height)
Top Overlay:
  region: 1552.11,1308.13 ccw(c1570,1299.19) 1587.89,1308.13 1570,1329.19
  lines w10: 1552.11,1308.13 ccw(c1570,1299.19) 1587.89,1308.13 1570,1329.19 1552.11,1308.13 ; 1580.5,1279.5 ccw(c1630,1230) 1679.5,1279.5 1630,1330 1580.5,1279.5
  text "%" at 1590,1190 h80
  text "VCC" at 1620,1030 h30
  text "SCL" at 1620,930 h30
  text "SDA" at 1620,830 h30
  text "GND" at 1620,730 h30
  text "CR2032" at 220,640 h30
  text "'.PRJ_Title'" at 500,560 h50
  text "'.PRJ_Number'.PCB_Rev" at 530,510 h50
  text "V" at 1040,150 h30
  text "T" at 1140,150 h30
  text "R" at 1240,150 h30
  text "G" at 1340,150 h30
  text ".Layer_Name" at 577,-1628.49 h60
Bottom Overlay:
  region: 1738.13,387.89 ccw(c1729.19,370) 1738.13,352.11 1759.19,370
  lines w10: 1709.5,260.5 cw(c1660,310) 1709.5,359.5 1760,310 1709.5,260.5 ; 1738.13,352.11 cw(c1729.19,370) 1738.13,387.89 1759.19,370 1738.13,352.11
  text "S1" at 60,890 h50 r270
  text "S2" at 60,490 h50 r270
  text "HDC2010  / Humidity Sensor" at 1600,440 h72.83 r270
  text "%" at 1614.63,273.93 h80 r270
  text ".Layer_Name" at 577,-1628.49 h60
Top Paste:
  text ".Layer_Name" at 577,-1628.49 h60
Bottom Paste:
  text ".Layer_Name" at 577,-1628.49 h60
Top Solder:
  text ".Layer_Name" at 577,-1628.49 h60
  text ".Layer_Name" at 577,-1628.49 h60
Bottom Solder:
  text ".Layer_Name" at 577,-1628.49 h60
Drill Guide:
  text ".Layer_Name" at 577,-1628.49 h60
M1 Board Outline:
  region: 1569.53,1104.01 ccw(c1572.6,1111.42) 1580.61,1111.42 ccw(c1572.6,1111.42) 1575.66,1118.82 cw(c1630,1250) 1771.99,1250 cw(c1630,1250) 1684.34,1118.82 ccw(c1687.4,1111.42) 1690.47,1104.01 ccw(c1630,1250) 1788.02,1250 ccw(c1630,1250)
  lines w16: -8,0 ccw(c0,0) 0,-8 ; -8,0 ccw(c0,0) 0,-8 ; -8,0 -8,1450 ; -8,1450 cw(c0,1450) 0,1458 ; -8,1450 cw(c0,1450) 0,1458 ; 0,-8 1830,-8 ; 0,1458 1830,1458 ; 1567.96,1100.33 ccw(c1630,1250) 1568,1100.32 ; 1567.96,1100.33 cw(c1630,1250) 1792.01,1250 cw(c1630,1250) 1692.04,1100.33 ; 1567.96,1100.33 cw(c1564.94,1092.93) 1568,1100.32 ; 1568,1100.32 ccw(c1572.6,1111.42) 1584.61,1111.42 ccw(c1572.6,1111.42) 1577.22,1122.51 ; 1577.2,1122.52 cw(c1630,1250) 1767.99,1250 cw(c1630,1250) 1682.81,1122.52 ; 1577.22,1122.51 ccw(c1572.6,1111.42) 1577.2,1122.52 ; 1577.2,1122.52 ccw(c1580.26,1129.91) 1577.22,1122.51 ; 1682.78,1122.51 ccw(c1679.74,1129.91) 1682.81,1122.52 ; 1682.78,1122.51 ccw(c1687.4,1111.42) 1691.97,1100.31 ; 1682.81,1122.52 ccw(c1687.4,1111.42) 1682.78,1122.51 ; 1691.97,1100.31 cw(c1695.06,1092.93) 1692.04,1100.33 ; 1691.97,1100.31 ccw(c1687.4,1111.42) 1692,1100.32 ; 1692,1100.32 ccw(c1630,1250) 1692.04,1100.33 ; 1692,1100.32 cw(c1695.06,1092.93) 1692.04,1100.33 ; 1830,-8 ccw(c1830,0) 1838,0 ; 1830,-8 ccw(c1830,0) 1838,0 ; 1830,1458 cw(c1830,1450) 1838,1450 ; 1830,1458 cw(c1830,1450) 1838,1450 ; 1838,0 1838,1450
  lines w40: 1572.6,1111.42 cw(c1630,1250) 1687.4,1111.42
  text ".Layer_Name" at 577,-1628.49 h60
M2 Board Dimensions:
  rectangle: 125,-1170 500,-1045
  rectangle: 0,-1045 125,-920
  lines w7: 0,-1045 1000,-1045 ; 125,-1170 125,-920 ; 250,-1170 250,-920 ; 500,-1170 500,-920 ; 750,-1170 750,-920 ; 0,-1170 0,-920 1000,-920 1000,-1170 0,-1170
  text ".Layer_Name" at 577,-1628.49 h60
M3 3D STEP Top:
  text ".Layer_Name" at 577,-1628.49 h60
M4 3D STEP Bottom:
  text ".Layer_Name" at 577,-1628.49 h60
M5 Assembly Top:
  lines w10: -292,-1700.17 6308,-1700.17 ; -292,-1496.83 6310,-1496.83 ; -292,-1293.5 -292,-1903.5 3713,-1903.5 6310,-1903.5 6310,-1293.5 -291.5,-1293.5 -291.5,-1903.5 1284,-1903.5 ; 2173,-1903.5 2173,-1293.5 ; 3440,-1496.83 3440,-1293.5 ; 4280,-1496.83 4280,-1293.5 ; 4902,-1910 4902,-1707.17
  text "COMPONENTS MARKED 'DNP' SHOULD NOT BE POPULATED." at 1153.5,-1088.5 h60
  text "ASSEMBLY VARIANT:" at 1153,-1204 h60
  text ".VariantName" at 2189,-1204 h60
  text "PCB VIEWED FROM TOP SIDE" at -228.5,-1425.67 h60
  text "BOARD #:" at 2248,-1425.67 h60
  text ".PRJ_Number" at 2793.5,-1425.67 h60
  text "REV:" at 3638,-1425.67 h60
  text ".PCB_Rev" at 3929.5,-1425.67 h60
  text "SVN REV:" at 4476,-1425.67 h60
  text ".VersionControl_RevNumber" at 4982,-1425.67 h60
  text "TID #:" at 2248,-1629 h60
  text ".TID" at 2793.5,-1629 h60
  text "PLOT NAME =" at -228.5,-1834.34 h60
  text ".plot_File_Name" at 577,-1834.34 h60
  text "GENERATED    :" at 2250,-1834.34 h60
  text ".Print_Date" at 3119.5,-1834.34 h60
  text ".Print_Time" at 3848.5,-1834.34 h60
  text "TEXAS INSTRUMENTS" at 5113,-1834.34 h60
M6 Assembly Bottom:
  lines w10: -292.5,-1497.33 6309.5,-1497.33 ; -290.5,-1700.67 6309.5,-1700.67 ; 1115.5,-1910.5 1115.5,-1707.67 ; 1600,1360 1630,1330 ; 1660,1360 1630,1330 ; 1737.5,-1497.33 1737.5,-1294 ; 2577.5,-1497.33 2577.5,-1294 ; 3844.5,-1904 3844.5,-1294 ; 4733.5,-1904 6309,-1904 6309,-1294 -292.5,-1294 -292.5,-1904 2304.5,-1904 6309.5,-1904 6309.5,-1294 ; 1630,1330 1630,1600 ; 1630,1600 3760,1600 3760,1690 1650,1690 1630,1690 1630,1600
  text "HDC device must not be submerged in cleaning solution." at 3730,1620 h40
  text "COMPONENTS MARKED 'DNP' SHOULD NOT BE POPULATED." at 6102,-1088 h60
  text ".VariantName" at 5058,-1204 h60
  text "ASSEMBLY VARIANT:" at 6097,-1204 h60
  text ".VersionControl_RevNumber" at 1035.5,-1426.17 h60
  text "SVN REV:" at 1541.5,-1426.17 h60
  text ".PCB_Rev" at 2088,-1426.17 h60
  text "REV:" at 2379.5,-1426.17 h60
  text ".PRJ_Number" at 3224,-1426.17 h60
  text "BOARD #:" at 3769.5,-1426.17 h60
  text "PCB VIEWED FROM BOTTOM SIDE" at 6246,-1426.17 h60
  text ".TID" at 3224,-1629.5 h60
  text "TID #:" at 3769.5,-1629.5 h60
  text "TEXAS INSTRUMENTS" at 904.5,-1834.84 h60
  text ".Print_Time" at 2169,-1834.84 h60
  text ".Print_Date" at 2898,-1834.84 h60
  text "GENERATED    :" at 3767.5,-1834.84 h60
  text ".plot_File_Name" at 5440.5,-1834.84 h60
  text "PLOT NAME =" at 6246,-1834.84 h60
M9 Title Sheet:
  drawing of 57 lines, arcs and shapes, not listed
  text "1" at 739.84,7266.5 h70
  text "2" at 3235.5,7266.5 h70
  text "3" at 5724.84,7266.5 h70
  text "4" at 8231.51,7266.5 h70
  text "5" at 10730.5,7266.5 h70
  text "6" at 13235.5,7266.5 h70
  text "A" at -416.5,6123.5 h70
  text "A" at 14383.5,6123.5 h70
  text "B" at -416.5,3743.5 h70
  text "B" at 14383.5,3743.5 h70
  text "C" at -416.5,1368.5 h70
  text "C" at 14383.5,1368.5 h70
  text "PROJECT TITLE:" at 11343.5,-492.5 h45
  text ".PRJ_Title" at 11393.5,-625.83 h70
  text "DESIGNED FOR:" at 11343.5,-793.5 h45
  text ".PRJ_Customer" at 11393.5,-933.5 h70
  text "D" at -416.5,-1001.5 h70
  text "D" at 14383.5,-1001.5 h70
  text "FILE NAME:" at 11343.5,-1093.5 h45
  text ".PCB_File_Name_No_Path" at 11393.5,-1213.5 h70
  text "Texas Instruments (TI) and/or its licensors do not warrant the accuracy or completeness of this specification" at 6374,-1375.34 h45
  text "ENGINEER:" at 11343.5,-1383.5 h45
  text "LAYOUT BY:" at 12848.5,-1383.5 h45
  text "or any information contained therein. TI and/or its licensors do not warrant that this design will meet" at 6329.01,-1488 h45
  text ".PRJ_Engineer" at 11393.5,-1538.49 h70
  text ".PCB_Layout" at 12899,-1538.49 h70
  text "the specifications, will be suitable for your application or fit for any particular purpose, or will operate in" at 6329.01,-1600.67 h45
  text ".Layer_Name" at 577,-1628.49 h60
  text "ALTIUM DESIGNER VERSION:" at 12848.5,-1693.5 h45
  text "an implementation. TI and/or its licensors do not warrant that the design is production worthy. You should" at 6329.01,-1713.33 h45
  text "completely validate and test your design implementation to confirm the system functionality for your application." at 6374,-1826 h45
  text ".print_Scale" at 11393.5,-1826.83 h70
  text ".Application_BuildNumber" at 12899,-1826.83 h70
  text "1" at 739.84,-2033.5 h70
  text "2" at 3235.5,-2033.5 h70
  text "3" at 5724.84,-2033.5 h70
  text "4" at 8231.51,-2033.5 h70
  text "5" at 10730.5,-2033.5 h70
  text "6" at 13235.5,-2033.5 h70
M10 Fab Notes:
  drawing of 173 lines, arcs and shapes, not listed
  text "DESIGN INFORMATION" at 12378.02,5431 h60
  text "MIN. TRACK WIDTH:" at 11733.46,5251 h60
  text "8" at 12829.7,5251 h60
  text "MIL" at 12984.46,5251 h60
  text "MIN. CLEARANCE:" at 11733.46,5119 h60
  text "0.2" at 12769.7,5119 h60
  text "mm" at 12984.46,5119 h60
  text "MIN. VIA PAD SIZE:" at 11733.46,4987 h60
  text "24" at 12799.71,4987 h60
  text "MIL" at 12984.46,4987 h60
  text "0.05mm (2MIL)" at 12428.46,4845.29 h60
  text "MINIMUM ANNULAR RING" at 11404.23,4841 h60
  text "EXTERNAL" at 13136.46,4841 h60
  text "PER" at 11604.23,4723 h60
  text "IPC-D-275 CLASS 2 LEVEL C" at 11824.23,4723 h60
  text "MIL, HOLES" at 13312.46,4610.71 h60
  text "+/-" at 12920,4610 h60
  text "+/-" at 13774,4610 h60
  text "REGISTRATION TOLERANCES:" at 11404.23,4605 h60
  text "METAL" at 12604,4605 h60
  text "5" at 13180.2,4605 h60
  text "3" at 14013.2,4605 h60
  text "MIL" at 14129.46,4605 h60
  text "+/-" at 13774,4492 h60
  text "HOLE SIZE TOLERANCE (UNLESS OTHERWISE SPECIFIED):" at 11404.23,4487 h60
  text "3" at 14013.2,4487 h60
  text "MIL" at 14129.46,4487 h60
  text "MATERIAL:" at 11329.46,4277.54 h60
  text "FR-4 High Tg" at 12315.9,4137.21 h60
  text "FR-408" at 11750.46,4128.64 h60
  text "OTHER" at 13238.46,4128.64 h60
  text "X" at 12161,4125 h60
  text "62 MIL (1.6mm) +/-10%" at 12070.56,3965.92 h60
  text "THICKNESS:" at 11404.23,3961.64 h60
  text "X" at 11942.4,3961.64 h60
  text "OTHER" at 13355.46,3961.64 h60
  text "TOLERANCE:" at 11404.23,3803.64 h60
  text "X" at 12243.53,3803.64 h60
  text "ANSI IPC-6012 TYPE 3 CLASS 2" at 12430.48,3803.64 h60
  text "OTHER +/-" at 12430.46,3647.64 h60
  text "BOW & TWIST:" at 11404.23,3490.64 h60
  text "X" at 12243.53,3490.64 h60
  text "ANSI IPC-6012 TYPE 3 CLASS 2" at 12430.48,3490.64 h60
  text "OTHER +/-" at 12430.46,3332.13 h60
  text "DRILLING:" at 11329.46,3193.64 h60
  text "REFERENCE:" at 11404.23,3076.64 h60
  text "X" at 12052.46,3076.64 h60
  text "AS SHOWN" at 12239.46,3076.64 h60
  text "X" at 12953.46,3076.64 h60
  text "NC_DRILL FILES" at 13090.46,3076.64 h60
  text "PTH COPPER THICKNESS:" at 11404.23,2918.64 h60
  text "X" at 12534.46,2918.64 h60
  text "20-30 um" at 12671.46,2918.64 h60
  text "OTHER" at 13388.46,2918.64 h60
  text "BOARD FINISH:" at 11329.46,2759.64 h60
  text "SILKSCREEN:" at 11484.68,2641.64 h60
  text "X" at 12433.46,2641.64 h60
  text "TOP" at 12559.46,2641.64 h60
  text "X" at 12943.46,2641.64 h60
  text "BOTTOM" at 13070.46,2641.64 h60
  text "SILKSCREEN COLOR:" at 11484.68,2474.64 h60
  text "X" at 12432.42,2474.64 h60
  text "WHITE" at 12559.46,2474.64 h60
  text "OTHER" at 13070.46,2474.64 h60
  text "X" at 13150,2320 h60
  text "GREEN" at 12690.46,2315.44 h60
  text "OTHER" at 13308.46,2315.44 h60
  text "RED" at 13770,2310 h72.83
  text "SOLDER RESIST COLOR:" at 11484.68,2304.64 h60
  text "MATTE" at 12690.46,2145.44 h60
  text "SEMI-GLOSS" at 13308,2144.8 h60
  text "IMMERSION GOLD (ENIG)" at 12390.46,1956.92 h60
  text "ENEPIG" at 13728,1953.64 h60
  text "SURFACE FINISH:" at 11329.46,1952.64 h60
  text "X" at 12203.51,1952.64 h60
  text "IMM. TIN/SILVER OR EQUIV" at 11659,1795.64 h60
  text "OTHER" at 13090.46,1795.64 h60
  text "ARRAY/PANEL:" at 11329.46,1616.64 h60
  text "CUT AND TRIM PER M1 BOARD OUTLINE" at 12390.46,1612.35 h60
  text "X" at 12210,1610 h60
  text "N.C. ROUTE" at 12390.46,1460.64 h60
  text "V. SCORE" at 13256.46,1460.64 h60
  text "CERTIFICATION:" at 11329.46,1323.64 h60
  text "MATERIALS AND WORKMANSHIP FOR ALL PCBS" at 12054.46,1323.64 h60
  text "TO MEET OR EXCEED THE REQUIREMENTS OF:" at 12054.46,1225.64 h60
  text "X" at 11680.96,1089.13 h60
  text "ANSI IPC-A-600F CLASS ->" at 11819.96,1089.13 h60
  text "X" at 13459.02,1089.13 h60
  text "2" at 13577.96,1089.14 h60
  text "1" at 13262.96,1087.64 h60
  text "3" at 13931.96,1087.64 h60
  text "X" at 12495.02,929.64 h60
  text "RoHS" at 12631.96,929.64 h60
  text "OTHER" at 13276.36,929.64 h60
  text "PER ORDER" at 13673.42,929.64 h60
  text "ALL BOARDS MUST MEET OR EXCEED UL94-V0 REQUIREMENTS." at 11357,764 h60
  text "PCB MUST BEAR THE UL94V-0 UL REGISTERED MATERIAL ID NUMBER" at 11357,644 h60
  text "ADDITIONAL REQUIREMENTS:" at 11329.46,470.64 h60
  text "MICROSECTION:" at 11404.23,355.64 h60
  text "YES" at 12309.96,355.64 h60
  text "REQUIRED" at 13171.46,199.49 h60
  text "BARE BOARD ELEC. TEST:" at 11404.23,196.64 h60
  text "NONE" at 12709.96,196.64 h60
  text "X" at 13044.46,196.64 h60
  text "PER ORDER" at 13763.46,196.64 h60
  text ".Layer_Name" at 577,-1628.49 h60
M11 Gerber Information:
  lines w10: -292,-1700.17 6308,-1700.17 ; -292,-1496.83 6310,-1496.83 ; -292,-1293.5 -292,-1903.5 3713,-1903.5 6310,-1903.5 6310,-1293.5 -291.5,-1293.5 -291.5,-1903.5 1284,-1903.5 ; 2173,-1903.5 2173,-1293.5 ; 3440,-1496.83 3440,-1293.5 ; 4280,-1496.83 4280,-1293.5 ; 4902,-1910 4902,-1707.17
  text "ALL ARTWORK VIEWED FROM TOP SIDE" at -228.5,-1425.67 h60
  text "BOARD #:" at 2248,-1425.67 h60
  text ".PRJ_Number" at 2793.5,-1425.67 h60
  text "REV:" at 3638,-1425.67 h60
  text ".PCB_Rev" at 3929.5,-1425.67 h60
  text "SVN REV:" at 4476,-1425.67 h60
  text ".VersionControl_RevNumber" at 4982,-1425.67 h60
  text "LAYER NAME =" at -228.5,-1628.49 h60
  text "TID #:" at 2248,-1629 h60
  text ".TID" at 2793.5,-1629 h60
  text "PLOT NAME =" at -228.5,-1834.34 h60
  text ".plot_File_Name" at 577,-1834.34 h60
  text "GENERATED    :" at 2250,-1834.34 h60
  text ".Print_Date" at 3119.5,-1834.34 h60
  text ".Print_Time" at 3848.5,-1834.34 h60
  text "TEXAS INSTRUMENTS" at 5113,-1834.34 h60
M12 Stackup:
  drawing of 191 lines, arcs and shapes, not listed
  text "Layer" at 9790.34,7060 h60
  text "Name" at 10200.26,7060 h60
  text "Material" at 11130,7060 h60
  text "Thickness" at 11989.77,7060 h60
  text "Constant" at 12639.6,7060 h60
  text "Board Layer Stack" at 13209.46,7060 h60
  text "1" at 9790.34,6940 h60
  text "Top Overlay" at 10200.26,6940 h60
  text "2" at 9790.34,6820 h60
  text "Top Solder" at 10200.26,6820 h60
  text "Solder Resist" at 11130,6820 h60
  text "0.40mil" at 11989.77,6820 h60
  text "3.5" at 12639.6,6820 h60
  text "3" at 9790.34,6700 h60
  text "Top Layer" at 10200.26,6700 h60
  text "Copper" at 11130,6700 h60
  text "1.40mil" at 11989.77,6700 h60
  text "4" at 9790.34,6580 h60
  text "Dielectric1" at 10200.26,6580 h60
  text "FR-4" at 11130,6580 h60
  text "59.20mil" at 11989.77,6580 h60
  text "4.8" at 12639.6,6580 h60
  text "5" at 9790.34,6460 h60
  text "Bottom Layer" at 10200.26,6460 h60
  text "Copper" at 11130,6460 h60
  text "1.40mil" at 11989.77,6460 h60
  text "6" at 9790.34,6340 h60
  text "Bottom Solder" at 10200.26,6340 h60
  text "Solder Resist" at 11130,6340 h60
  text "0.40mil" at 11989.77,6340 h60
  text "3.5" at 12639.6,6340 h60
  text "7" at 9790.34,6220 h60
  text "Bottom Overlay" at 10200.26,6220 h60
  text ".Layer_Name" at 577,-1628.49 h60
M13 Component Bodies Top:
  text ".Layer_Name" at 577,-1628.49 h60
M14 Component Bodies Bottom:
  text ".Layer_Name" at 577,-1628.49 h60
M15 Courtyards Top:
  text ".Layer_Name" at 577,-1628.49 h60
M16 Courtyards Bottom:
  text ".Layer_Name" at 577,-1628.49 h60
Drill Drawing:
  lines w10: 0,0 0,1450 1830,1450 1830,0 0,0 ; 5336.16,2233.18 5349.99,2233.18 5363.82,2219.35 5377.66,2233.18 5391.49,2233.18 5377.66,2247.02 5391.49,2260.85 5377.66,2260.85 5363.82,2274.68 5349.99,2260.85 5336.16,2260.85 5349.99,2247.02 5336.16,2233.18 ; 5336.16,2357.68 5349.99,2357.68 5349.99,2343.85 5377.66,2343.85 5377.66,2357.68 5391.49,2357.68 5391.49,2385.35 5377.66,2385.35 5377.66,2399.18 5349.99,2399.18 5349.99,2385.35 5336.16,2385.35 5336.16,2357.68 ; 5336.16,2523.68 5391.49,2523.68 5363.82,2468.35 5336.16,2523.68
  lines w12: 5286,2182 8518.19,2182 ; 5286,2555.5 8518.19,2555.5 ; 5624.01,2057.5 5624.01,2680 ; 5956.17,2057.5 5956.17,2680 ; 6592.65,2057.5 6592.65,2680 ; 6851.85,2057.5 6851.85,2680 ; 7227.09,2057.5 7227.09,2680 ; 7951.64,2057.5 7951.64,2680 ; 5286,2057.5 8518.19,2057.5 8518.19,2680 5286,2680 5286,2057.5
  text "Symbol" at 5360.7,2592.85 h72
  text "Quantity" at 5661.36,2592.85 h72
  text "Finished Hole Size" at 5993.52,2592.85 h72
  text "Plated" at 6630,2592.85 h72
  text "Hole Type" at 6889.2,2592.85 h72
  text "Drill Layer Pair" at 7264.44,2592.85 h72
  text "Hole Tolerance" at 7988.99,2592.85 h72
  text "12" at 5661.36,2468.35 h60
  text "7.87mil (0.200mm)" at 5993.52,2468.35 h60
  text "PTH" at 6630,2468.35 h60
  text "Round" at 6889.2,2468.35 h60
  text "Top Layer - Bottom Layer" at 7264.44,2468.35 h60
  text "49" at 5661.36,2343.85 h60
  text "10.00mil (0.254mm)" at 5993.52,2343.85 h60
  text "PTH" at 6630,2343.85 h60
  text "Round" at 6889.2,2343.85 h60
  text "Top Layer - Bottom Layer" at 7264.44,2343.85 h60
  text "4" at 5661.36,2219.35 h60
  text "40.00mil (1.016mm)" at 5993.52,2219.35 h60
  text "PTH" at 6630,2219.35 h60
  text "Round" at 6889.2,2219.35 h60
  text "Top Layer - Bottom Layer" at 7264.44,2219.35 h60
  text "65 Total" at 5661.36,2094.85 h60
  text ".Layer_Name" at 577,-1628.49 h60
M17 Embedded Cavity:
  text ".Layer_Name" at 577,-1628.49 h60
M18 Embedded Assembly:
  text ".Layer_Name" at 577,-1628.49 h60
M19 Embedded Keepout:
  text ".Layer_Name" at 577,-1628.49 h60

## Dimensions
0,0 to 0,1450 on M2 Board Dimensions
0,0 to 1830,0 on M2 Board Dimensions
0,-1170 to 1000,-1170 on M2 Board Dimensions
